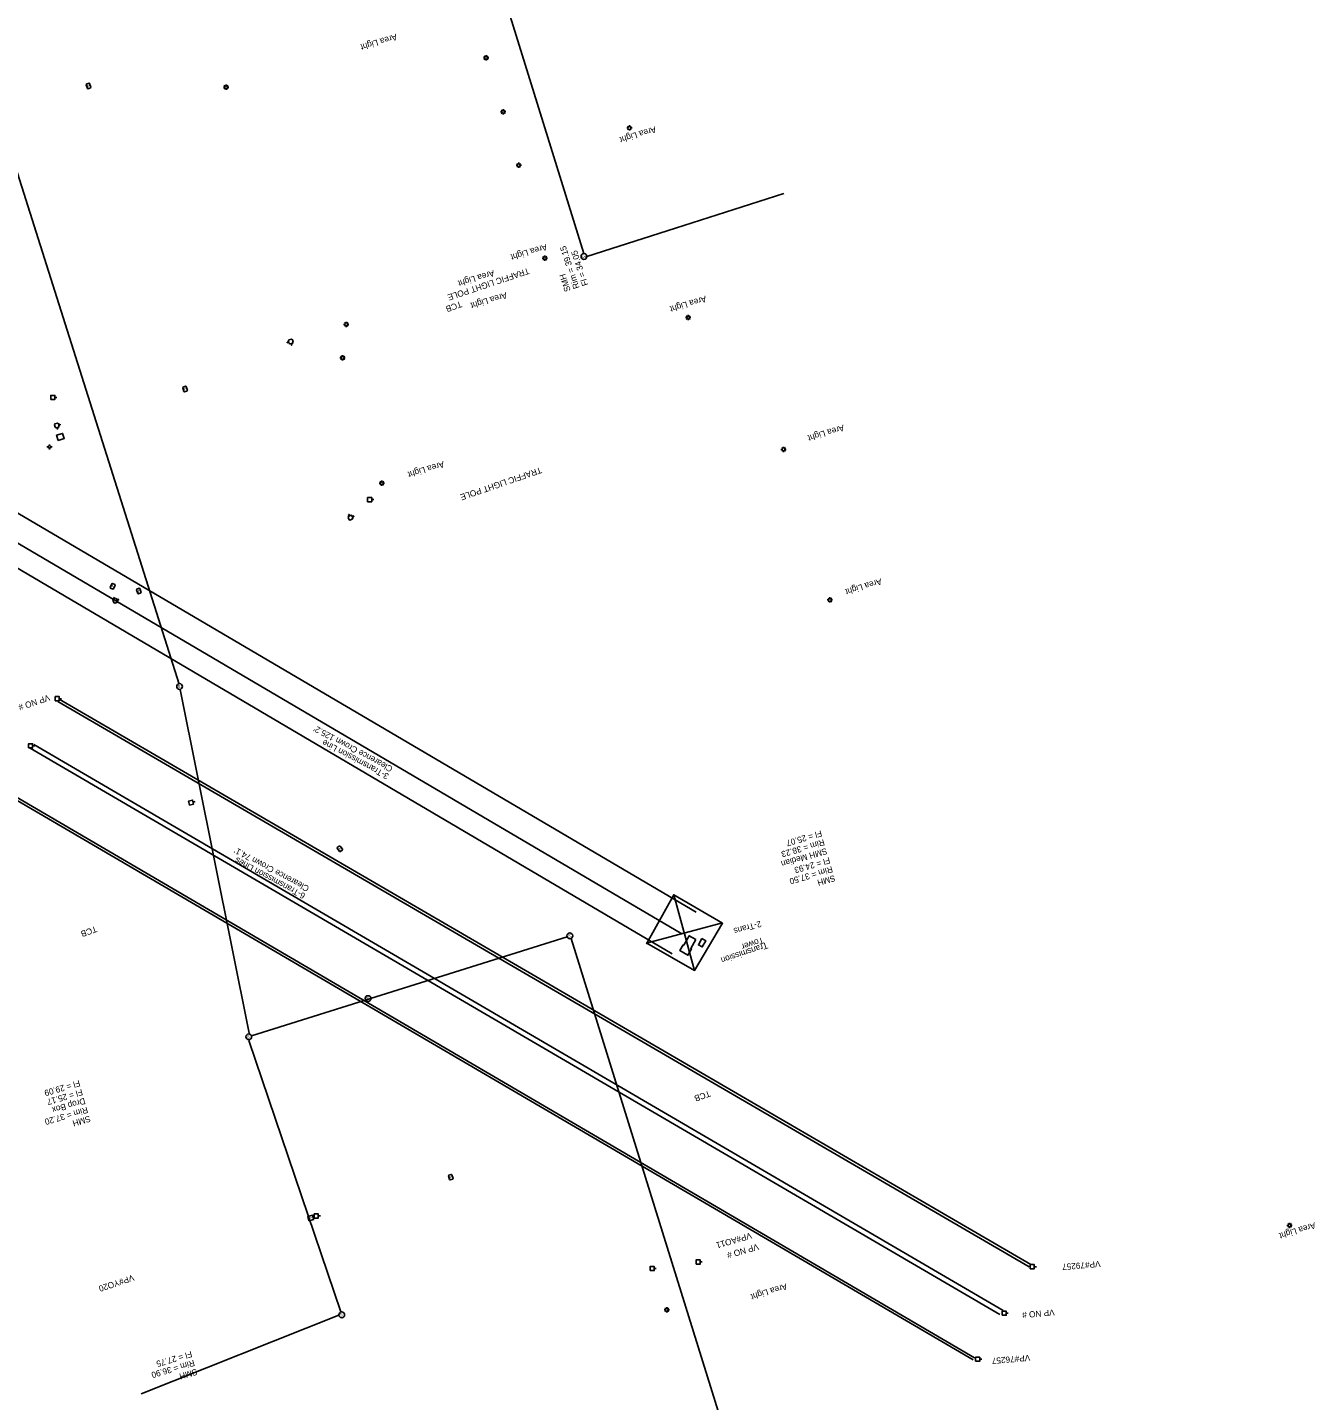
# Model space of a CAD drawing. Extents: x 3872070 to 3879223, y 293944 to 310567.
# Drawn here: x 3876007 to 3876634, y 301626 to 302295 of the extents above; entities that cross this region are included whole.
import ezdxf

# ---------------------------------------------------------------- set-up
doc = ezdxf.new("R2010")
doc.units = 0
for name, color, linetype in [('Level 3', 7, 'Continuous'), ('Level 33', 7, 'Continuous'), ('Level 34', 7, 'Continuous'), ('Level 39', 7, 'Continuous'), ('Level 4', 7, 'Continuous'), ('Level 5', 7, 'Continuous'), ('Level 7', 7, 'Continuous'), ('Level 9', 7, 'Continuous')]:
    doc.layers.add(name, color=color, linetype=linetype)

msp = doc.modelspace()

# ---------------------------------------------------------------- linework, layer by layer
at = {"layer": 'Level 3'}
for p, q in [((3876277.89, 302185), (3876189.68, 302468.6)), ((3876080.68, 301975.37), (3875980.32, 302292.19)), ((3876375.32, 302214.14), (3876322.5, 302197.29)), ((3876322.5, 302197.29), (3876279.3, 302183.52)), ((3876114.75, 301805.31), (3876081.18, 301972.71)), ((3876269.68, 301852.28), (3876115.99, 301804.03)), ((3876447.11, 301287.36), (3876271.58, 301851.5)), ((3876159.39, 301669.6), (3876114.57, 301801.76)), ((3876158.47, 301668.04), (3876062.18, 301629.7))]:
    msp.add_line(p, q, dxfattribs=at)
for centre in [(3876277.9, 302183.52), (3876080.91, 301974.15), (3876271.01, 301852.78), (3876172.7, 301822.21), (3876114.6, 301803.63), (3876159.9, 301668.19)]:
    msp.add_circle(centre, 1.41, dxfattribs=at)
at = {"layer": 'Level 4'}
for p, q in [((3876229.44, 302280.26), (3876228.87, 302280.26)), ((3876229.66, 302280.77), (3876229.25, 302281.18)), ((3876229.25, 302279.34), (3876229.66, 302279.74)), ((3876230.17, 302280.98), (3876230.17, 302281.56)), ((3876230.17, 302279.53), (3876230.17, 302278.96)), ((3876230.68, 302280.77), (3876231.09, 302281.18)), ((3876231.09, 302279.34), (3876230.68, 302279.74)), ((3876230.89, 302280.26), (3876231.47, 302280.26)), ((3876103.02, 302266.48), (3876102.62, 302266.89)), ((3876103.54, 302266.69), (3876103.54, 302267.27)), ((3876104.05, 302266.48), (3876104.46, 302266.89)), ((3876102.81, 302265.97), (3876102.24, 302265.97)), ((3876102.62, 302265.05), (3876103.02, 302265.45)), ((3876103.54, 302265.24), (3876103.54, 302264.67)), ((3876104.46, 302265.05), (3876104.05, 302265.45)), ((3876104.26, 302265.97), (3876104.84, 302265.97)), ((3876237.8, 302253.95), (3876237.23, 302253.95)), ((3876238.01, 302254.47), (3876237.61, 302254.87)), ((3876237.61, 302253.03), (3876238.01, 302253.44)), ((3876238.52, 302254.68), (3876238.52, 302255.25)), ((3876238.52, 302253.23), (3876238.52, 302252.65)), ((3876239.04, 302254.47), (3876239.44, 302254.87)), ((3876239.44, 302253.03), (3876239.04, 302253.44)), ((3876239.25, 302253.95), (3876239.83, 302253.95)), ((3876299.27, 302246.11), (3876298.69, 302246.11)), ((3876299.48, 302246.62), (3876299.08, 302247.03)), ((3876299.99, 302246.83), (3876299.99, 302247.41)), ((3876300.51, 302246.62), (3876300.91, 302247.03)), ((3876300.72, 302246.11), (3876301.29, 302246.11)), ((3876299.08, 302245.19), (3876299.48, 302245.59)), ((3876299.99, 302245.38), (3876299.99, 302244.81)), ((3876300.91, 302245.19), (3876300.51, 302245.59)), ((3876245.37, 302227.96), (3876244.79, 302227.96)), ((3876245.58, 302228.47), (3876245.17, 302228.88)), ((3876245.17, 302227.04), (3876245.58, 302227.44)), ((3876246.09, 302228.68), (3876246.09, 302229.26)), ((3876246.09, 302227.23), (3876246.09, 302226.66)), ((3876246.61, 302228.47), (3876247.01, 302228.88)), ((3876247.01, 302227.04), (3876246.61, 302227.44)), ((3876246.82, 302227.96), (3876247.39, 302227.96)), ((3876332.58, 301864.21), (3875730.81, 302218.1)), ((3876325.63, 301853.67), (3875723.85, 302207.56)), ((3876320.83, 301844.07), (3875719.05, 302197.96)), ((3876258.11, 302182.75), (3876257.54, 302182.75)), ((3876258.32, 302183.26), (3876257.92, 302183.66)), ((3876257.92, 302181.83), (3876258.32, 302182.23)), ((3876258.84, 302183.47), (3876258.84, 302184.05)), ((3876258.84, 302182.02), (3876258.84, 302181.45)), ((3876259.35, 302183.26), (3876259.75, 302183.66)), ((3876259.75, 302181.83), (3876259.35, 302182.23)), ((3876259.56, 302182.75), (3876260.14, 302182.75)), ((3876327.91, 302153.8), (3876327.34, 302153.8)), ((3876328.13, 302154.31), (3876327.72, 302154.72)), ((3876327.72, 302152.88), (3876328.13, 302153.28)), ((3876328.64, 302154.52), (3876328.64, 302155.1)), ((3876328.64, 302153.07), (3876328.64, 302152.5)), ((3876329.15, 302154.31), (3876329.56, 302154.72)), ((3876329.56, 302152.88), (3876329.15, 302153.28)), ((3876329.36, 302153.8), (3876329.94, 302153.8)), ((3876161.37, 302150.49), (3876160.79, 302150.49)), ((3876161.58, 302151), (3876161.17, 302151.41)), ((3876161.17, 302149.57), (3876161.58, 302149.98)), ((3876162.09, 302151.22), (3876162.09, 302151.79)), ((3876162.09, 302149.77), (3876162.09, 302149.19)), ((3876162.6, 302151), (3876163.01, 302151.41)), ((3876163.01, 302149.57), (3876162.6, 302149.98)), ((3876162.82, 302150.49), (3876163.39, 302150.49)), ((3876159.6, 302134.17), (3876159.02, 302134.17)), ((3876159.81, 302134.68), (3876159.41, 302135.09)), ((3876159.41, 302133.25), (3876159.81, 302133.66)), ((3876160.33, 302134.89), (3876160.33, 302135.47)), ((3876160.33, 302133.44), (3876160.33, 302132.87)), ((3876160.84, 302134.68), (3876161.24, 302135.09)), ((3876161.24, 302133.25), (3876160.84, 302133.66)), ((3876161.05, 302134.17), (3876161.62, 302134.17)), ((3876020.18, 302114.91), (3876021.18, 302114.91)), ((3876374.4, 302089.64), (3876373.82, 302089.64)), ((3876374.61, 302090.15), (3876374.2, 302090.56)), ((3876374.2, 302088.72), (3876374.61, 302089.12)), ((3876375.12, 302090.36), (3876375.12, 302090.94)), ((3876375.12, 302088.91), (3876375.12, 302088.34)), ((3876375.63, 302090.15), (3876376.04, 302090.56)), ((3876376.04, 302088.72), (3876375.63, 302089.12)), ((3876375.85, 302089.64), (3876376.42, 302089.64)), ((3876178.74, 302073.16), (3876178.17, 302073.16)), ((3876178.96, 302073.68), (3876178.55, 302074.08)), ((3876178.55, 302072.24), (3876178.96, 302072.65)), ((3876179.47, 302073.89), (3876179.47, 302074.46)), ((3876179.47, 302072.44), (3876179.47, 302071.86)), ((3876179.98, 302073.68), (3876180.39, 302074.08)), ((3876180.39, 302072.24), (3876179.98, 302072.65)), ((3876180.19, 302073.16), (3876180.77, 302073.16)), ((3876174.51, 302065.15), (3876175.51, 302065.15)), ((3876396.97, 302016.29), (3876396.4, 302016.29)), ((3876397.18, 302016.81), (3876396.78, 302017.21)), ((3876396.78, 302015.37), (3876397.18, 302015.78)), ((3876397.7, 302017.02), (3876397.7, 302017.59)), ((3876397.7, 302015.57), (3876397.7, 302014.99)), ((3876398.21, 302016.81), (3876398.61, 302017.21)), ((3876398.61, 302015.37), (3876398.21, 302015.78)), ((3876398.42, 302016.29), (3876399, 302016.29)), ((3876021.62, 301966.83), (3876494.79, 301691.59)), ((3876022.32, 301968.23), (3876023.32, 301968.23)), ((3876022.34, 301968.03), (3876495.51, 301692.78)), ((3876009.33, 301945.26), (3876010.33, 301945.26)), ((3876482.07, 301670.25), (3876009.86, 301945.98)), ((3876480.39, 301668.33), (3876008.18, 301944.06)), ((3875995.22, 301922.48), (3876467.43, 301646.27)), ((3875995.94, 301923.44), (3876468.15, 301647.23)), ((3876087.5, 301917.89), (3876088.47, 301918.12)), ((3876148.48, 301716.36), (3876149.48, 301716.36)), ((3876620.86, 301711.76), (3876620.29, 301711.76)), ((3876621.07, 301712.28), (3876620.67, 301712.68)), ((3876620.67, 301710.84), (3876621.07, 301711.25)), ((3876621.59, 301712.49), (3876621.59, 301713.06)), ((3876622.1, 301712.28), (3876622.51, 301712.68)), ((3876622.51, 301710.84), (3876622.1, 301711.25)), ((3876622.31, 301711.76), (3876622.89, 301711.76)), ((3876621.59, 301711.04), (3876621.59, 301710.46)), ((3876334.5, 301693.95), (3876335.5, 301693.95)), ((3876497.23, 301691.64), (3876498.23, 301691.64)), ((3876312.11, 301690.72), (3876313.11, 301690.72)), ((3876317.69, 301671.14), (3876317.29, 301671.55)), ((3876318.21, 301671.35), (3876318.21, 301671.93)), ((3876318.72, 301671.14), (3876319.12, 301671.55)), ((3876317.48, 301670.63), (3876316.91, 301670.63)), ((3876317.29, 301669.71), (3876317.69, 301670.12)), ((3876318.21, 301669.91), (3876318.21, 301669.33)), ((3876319.12, 301669.71), (3876318.72, 301670.12)), ((3876318.93, 301670.63), (3876319.5, 301670.63)), ((3876483.55, 301668.98), (3876484.55, 301668.98)), ((3876470.65, 301646.59), (3876471.65, 301646.59))]:
    msp.add_line(p, q, dxfattribs=at)
for points in [[(3876018.18, 302113.91), (3876018.18, 302115.91), (3876020.18, 302115.91), (3876020.18, 302113.91)], [(3876172.51, 302064.15), (3876172.51, 302066.15), (3876174.51, 302066.15), (3876174.51, 302064.15)], [(3876020.32, 301967.23), (3876020.32, 301969.23), (3876022.32, 301969.23), (3876022.32, 301967.23)], [(3876007.33, 301944.26), (3876007.33, 301946.26), (3876009.33, 301946.26), (3876009.33, 301944.26)], [(3876085.79, 301916.45), (3876085.32, 301918.4), (3876087.27, 301918.86), (3876087.73, 301916.91)], [(3876146.48, 301715.36), (3876146.48, 301717.36), (3876148.48, 301717.36), (3876148.48, 301715.36)], [(3876310.11, 301689.72), (3876310.11, 301691.72), (3876312.11, 301691.72), (3876312.11, 301689.72)], [(3876332.5, 301692.95), (3876332.5, 301694.95), (3876334.5, 301694.95), (3876334.5, 301692.95)], [(3876495.23, 301690.64), (3876495.23, 301692.64), (3876497.23, 301692.64), (3876497.23, 301690.64)], [(3876481.55, 301667.98), (3876481.55, 301669.98), (3876483.55, 301669.98), (3876483.55, 301667.98)], [(3876468.65, 301645.59), (3876468.65, 301647.59), (3876470.65, 301647.59), (3876470.65, 301645.59)]]:
    msp.add_lwpolyline(points, close=True, dxfattribs=at)
for points in [[(3876308.48, 301849.15), (3876331.77, 301835.92), (3876345.4, 301858.87), (3876321.65, 301872.77), (3876308.4, 301848.9), (3876308.48, 301849.15)], [(3876321.65, 301872.77), (3876331.77, 301835.92)], [(3876308.4, 301849.14), (3876345.4, 301859.11)], [(3876332.36, 301850.95), (3876329.86, 301846.61), (3876330.3, 301846.35), (3876328.54, 301843.3), (3876324.64, 301845.55), (3876326.22, 301848.3), (3876326.51, 301848.13), (3876329.18, 301852.78), (3876332.36, 301850.95)], [(3876335.35, 301851.38), (3876333.65, 301848.37), (3876335.5, 301847.32), (3876337.21, 301850.33), (3876335.35, 301851.38)]]:
    msp.add_lwpolyline(points, dxfattribs=at)
for centre in [(3876230.17, 302280.26), (3876103.54, 302265.97), (3876238.52, 302253.95), (3876299.99, 302246.11), (3876246.09, 302227.96), (3876258.84, 302182.75), (3876328.64, 302153.8), (3876162.09, 302150.49), (3876160.33, 302134.17), (3876375.12, 302089.64), (3876179.47, 302073.16), (3876397.7, 302016.29), (3876621.59, 301711.76), (3876318.21, 301670.63)]:
    msp.add_circle(centre, 0.725, dxfattribs=at)
at = {"layer": 'Level 5'}
for p, q in [((3876016.32, 302090.82), (3876016.94, 302090.82)), ((3876017.57, 302092.07), (3876017.57, 302091.44)), ((3876017.57, 302090.2), (3876017.57, 302089.57)), ((3876018.19, 302090.82), (3876018.82, 302090.82))]:
    msp.add_line(p, q, dxfattribs=at)
msp.add_circle((3876017.57, 302090.82), 0.625, dxfattribs=at)
at = {"layer": 'Level 7'}
msp.add_lwpolyline([(3876146.26, 301714.6), (3876143.94, 301714), (3876143.39, 301716.12), (3876145.71, 301716.72)], close=True, dxfattribs=at)
at = {"layer": 'Level 9'}
for p, q in [((3876135.21, 302141.12), (3876135.41, 302140.37)), ((3876135.66, 302140.43), (3876135.41, 302140.37)), ((3876135.45, 302141.18), (3876135.65, 302140.43)), ((3876022, 302101.63), (3876022.75, 302101.83)), ((3876022.06, 302101.39), (3876022.81, 302101.59)), ((3876022.75, 302101.83), (3876022.81, 302101.59)), ((3876163.24, 302057.88), (3876163.46, 302057.99)), ((3876163.59, 302057.18), (3876163.24, 302057.88)), ((3876163.81, 302057.3), (3876163.46, 302057.99)), ((3876048.75, 302017.38), (3876048.97, 302017.49)), ((3876049.1, 302016.68), (3876048.75, 302017.38)), ((3876049.32, 302016.8), (3876048.97, 302017.49))]:
    msp.add_line(p, q, dxfattribs=at)
for points in [[(3876036.02, 302265.4), (3876035.35, 302267.19), (3876035.5, 302267.51), (3876036.65, 302267.94), (3876036.97, 302267.79), (3876037.63, 302266), (3876037.48, 302265.68), (3876036.34, 302265.25)], [(3876133.38, 302141.53), (3876134.13, 302141.73), (3876134.07, 302141.97), (3876133.32, 302141.77)], [(3876136.2, 302141.76), (3876135.86, 302143), (3876135.43, 302143.25), (3876134.18, 302142.91), (3876133.93, 302142.48), (3876134.27, 302141.23), (3876134.71, 302140.98), (3876135.95, 302141.32)], [(3876135.66, 302140.43), (3876135.45, 302141.19), (3876135.21, 302141.12), (3876135.41, 302140.37)], [(3876083.04, 302117.82), (3876082.46, 302119.64), (3876082.63, 302119.95), (3876083.8, 302120.32), (3876084.11, 302120.16), (3876084.69, 302118.34), (3876084.52, 302118.02), (3876083.35, 302117.66)], [(3876021.43, 302102.39), (3876020.18, 302102.06), (3876019.93, 302101.62), (3876020.26, 302100.37), (3876020.69, 302100.12), (3876021.94, 302100.46), (3876022.19, 302100.89), (3876021.86, 302102.14)], [(3876021.64, 302099.57), (3876021.44, 302100.32), (3876021.2, 302100.26), (3876021.39, 302099.5)], [(3876022.75, 302101.83), (3876021.99, 302101.63), (3876022.06, 302101.39), (3876022.81, 302101.59)], [(3876021.75, 302094.02), (3876020.99, 302096.52), (3876023.94, 302097.41), (3876024.7, 302094.91)], [(3876162.97, 302056.47), (3876163.55, 302055.32), (3876164.03, 302055.16), (3876165.18, 302055.75), (3876165.34, 302056.22), (3876164.75, 302057.37), (3876164.28, 302057.53), (3876163.13, 302056.95)], [(3876163.24, 302057.88), (3876163.59, 302057.18), (3876163.81, 302057.3), (3876163.46, 302057.99)], [(3876165.69, 302057.26), (3876164.99, 302056.91), (3876165.1, 302056.69), (3876165.8, 302057.04)], [(3876047.1, 302022.41), (3876047.89, 302024.15), (3876048.22, 302024.27), (3876049.34, 302023.76), (3876049.46, 302023.43), (3876048.67, 302021.69), (3876048.33, 302021.57), (3876047.22, 302022.08)], [(3876060.54, 302019.49), (3876059.97, 302021.31), (3876060.13, 302021.63), (3876061.3, 302022), (3876061.62, 302021.83), (3876062.19, 302020.01), (3876062.03, 302019.7), (3876060.86, 302019.33)], [(3876048.48, 302015.97), (3876049.06, 302014.82), (3876049.54, 302014.66), (3876050.69, 302015.25), (3876050.85, 302015.72), (3876050.26, 302016.87), (3876049.79, 302017.03), (3876048.64, 302016.45)], [(3876048.75, 302017.38), (3876049.1, 302016.68), (3876049.32, 302016.8), (3876048.97, 302017.49)], [(3876051.2, 302016.76), (3876050.5, 302016.41), (3876050.61, 302016.19), (3876051.31, 302016.54)], [(3876158.88, 301893.88), (3876157.7, 301895.38), (3876157.74, 301895.73), (3876158.71, 301896.49), (3876159.06, 301896.45), (3876160.23, 301894.94), (3876160.19, 301894.59), (3876159.23, 301893.84)], [(3876212.45, 301734.06), (3876211.92, 301735.89), (3876212.09, 301736.2), (3876213.27, 301736.55), (3876213.58, 301736.38), (3876214.11, 301734.54), (3876213.94, 301734.23), (3876212.76, 301733.89)]]:
    msp.add_lwpolyline(points, close=True, dxfattribs=at)

# ---------------------------------------------------------------- texts
at = {"layer": 'Level 3'}
for rotation, p in [(270, (3876277.18, 302183.99)), (180, (3876081.39, 301974.87)), (180, (3876271.48, 301853.5)), (180, (3876173.17, 301822.92)), (180, (3876115.08, 301804.34)), (180, (3876160.37, 301668.9))]:
    msp.add_text('S', height=1.41, rotation=rotation, dxfattribs=at).set_placement(p)
at = {"layer": 'Level 33'}
for s, rotation, p in [('Rim = 39.15', 108.21449, (3876275.74, 302168.35)), ('Fl = 34.05', 108.21449, (3876280.02, 302169.76)), ('SMH', 108.21449, (3876271.47, 302166.95)), ('Rim = 38.23', 196.31202, (3876394.58, 301899.88)), ('Fl = 25.07', 196.31202, (3876393.31, 301904.19)), ('SMH Median', 196.31202, (3876395.84, 301895.56)), ('Rim = 37.50', 196.31202, (3876398.56, 301886.72)), ('Fl = 24.93', 196.31202, (3876397.3, 301891.04)), ('SMH', 196.31202, (3876399.83, 301882.4)), ('Fl = 29.09', 196.31202, (3876031.99, 301782.53)), ('Fl = 25.17', 196.31202, (3876033.25, 301778.21)), ('Drop Box', 196.31202, (3876034.52, 301773.89)), ('Rim = 37.20', 196.31202, (3876035.78, 301769.57)), ('SMH', 196.31202, (3876037.04, 301765.25)), ('Rim = 36.90', 196.31202, (3876087.77, 301646.34)), ('Fl = 27.75', 196.31202, (3876086.51, 301650.66)), ('SMH', 196.31202, (3876089.04, 301642.02))]:
    msp.add_text(s, height=3, rotation=rotation, dxfattribs=at).set_placement(p)
at = {"layer": 'Level 34'}
for s, rotation, p in [('Area Light', 196.76106, (3876186.32, 302292.01)), ('Area Light', 196.76106, (3876312.52, 302246.94)), ('Area Light', 196.76106, (3876259.45, 302189.72)), ('Area Light', 196.76106, (3876233.77, 302176.97)), ('Area Light', 196.76106, (3876239.89, 302166.19)), ('Area Light', 196.76106, (3876337, 302164.47)), ('Area Light', 196.76106, (3876404.18, 302101.65)), ('Area Light', 196.76106, (3876209.35, 302083.91)), ('Area Light', 196.76106, (3876422.41, 302026.84)), ('VP NO #', 198.45225, (3876017.13, 301970.26)), ("Clearence Crown 125.2'", 151.73939, (3876185.03, 301934.94)), ('3-Transmission Line', 151.73939, (3876183.14, 301931.42)), ("Clearence Crown 74.1'", 151.73939, (3876144.34, 301876.67)), ('6-Transmission Lines', 151.73939, (3876142.45, 301873.14)), ('2-Trans', 195.79675, (3876363.83, 301860.1)), (' Tower', 198.45225, (3876365.93, 301852.49)), ('Transmission', 198.45225, (3876366.89, 301849.62)), ('Area Light', 196.76106, (3876633.75, 301713.26)), ('VP#AO11', 196.14352, (3876359.1, 301708.34)), ('VP NO #', 196.14352, (3876362.48, 301702.92)), ('VP#79257', 184.89035, (3876529.34, 301694.55)), ('VP#YO20', 198.45225, (3876058.17, 301687.85)), ('Area Light', 196.76106, (3876376.36, 301683.56)), ('VP NO #', 184.89035, (3876506.98, 301670.91)), ('VP#76257', 184.89035, (3876495.1, 301648.83))]:
    msp.add_text(s, height=3, rotation=rotation, dxfattribs=at).set_placement(p)
at = {"layer": 'Level 39'}
for s, rotation, p in [('TRAFFIC LIGHT POLE', 198.42191, (3876250.68, 302178.05)), ('TCB', 199.72381, (3876217.77, 302161.88)), ('TRAFFIC LIGHT POLE', 198.91469, (3876256.68, 302081.06)), ('TCB', 199.72371, (3876040.02, 301857.6)), ('TCB', 199.72371, (3876338.84, 301777.5))]:
    msp.add_text(s, height=3, rotation=rotation, dxfattribs=at).set_placement(p)
at = {"layer": 'Level 7'}
msp.add_text('T', height=1.41, rotation=104.60387, dxfattribs=at).set_placement((3876145.71, 301715.01))
at = {"layer": 'Level 9'}
for rotation, p in [(20.3962, (3876036.3, 302265.79)), (17.49818, (3876083.35, 302118.19)), (335.33862, (3876047.57, 302022.48)), (17.49818, (3876060.85, 302019.86)), (38.00662, (3876159.03, 301894.33)), (16.18994, (3876212.76, 301734.43))]:
    msp.add_text('H', height=1.41, rotation=rotation, dxfattribs=at).set_placement(p)

doc.saveas('drawing.dxf')
